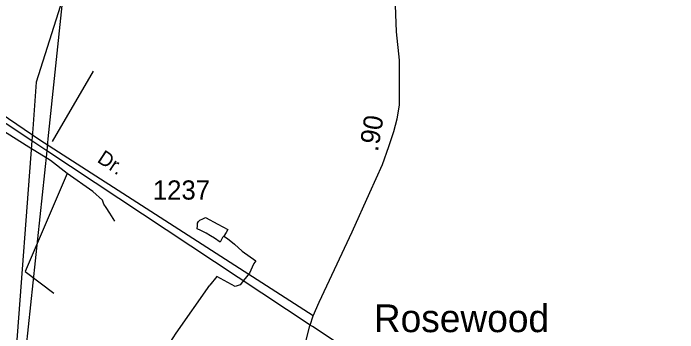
# Model space of a CAD drawing. Extents: x 2206922 to 2357709, y 510027 to 673830.
# Drawn here: x 2275145 to 2279467, y 607597 to 609677 of the extents above; entities that cross this region are included whole.
import ezdxf

# ---------------------------------------------------------------- set-up
doc = ezdxf.new("R2010")
doc.units = 0
for name, color, linetype in [('Exist Boundary Political Urban Extension UEB', 7, 'Continuous'), ('Exist Civil Demographics City Label', 7, 'Continuous'), ('Exist Hydrographic Creek Single Shore', 7, 'Continuous'), ('Exist Hydrographic Misc Water Feature', 7, 'Continuous'), ('Exist Railroad Mainline', 7, 'Continuous'), ('Exist Road Non-System Type 51', 7, 'Continuous'), ('Exist Road Primary NC Attributed', 7, 'Continuous'), ('Exist Road Primary NC Mileage Hundredths English Label', 7, 'Continuous'), ('Exist Road Secondary Type 51 Attributed', 7, 'Continuous'), ('Exist Road Secondary Type 51 Label', 7, 'Continuous'), ('Exist Road Secondary Type 51 Number Label', 7, 'Continuous'), ('Exist Utilities Electrical Transmission Line', 7, 'Continuous')]:
    doc.layers.add(name, color=color, linetype=linetype)

msp = doc.modelspace()

# ---------------------------------------------------------------- linework, layer by layer
at = {"layer": 'Exist Boundary Political Urban Extension UEB'}
for p, q in [((2275272.2, 608924.2), (2275266.2, 608845.4)), ((2275266.2, 608845.4), (2275143.8, 607237.3))]:
    msp.add_line(p, q, dxfattribs=at)
msp.add_lwpolyline([(2275466.5, 609770.2), (2275295.2, 609227.4), (2275272.2, 608924.2)], dxfattribs=at)
at = {"layer": 'Exist Hydrographic Creek Single Shore'}
msp.add_lwpolyline([(2275482.5, 602914), (2275367.6, 603398.5), (2275023.5, 604563.1), (2274947.7, 604653.2), (2274904.6, 604854.2), (2274802.5, 605059.5), (2274800.7, 605269.5), (2274932.5, 605453.7), (2275188.6, 605665), (2275493.5, 605990.1), (2275598.7, 606128.4), (2275699.6, 606261.3), (2275813.6, 606485.4), (2275951.6, 606863), (2276114.1, 607114.1), (2276154, 607168.5), (2276008.9, 607270.2), (2276088.7, 607411.7), (2276204.8, 607593.2), (2276424.7, 607906.1)], dxfattribs=at)
at = {"layer": 'Exist Hydrographic Misc Water Feature'}
for points in [[(2275804.9, 608324.2), (2275772.6, 608375.4), (2275748.6, 608413), (2275735.3, 608433.4), (2275724.7, 608460.9), (2275663.1, 608515.7), (2275496.2, 608633.4), (2275386.9, 608717.8), (2275229.8, 608816.1), (2275082.8, 608908.8), (2275017, 608952), (2274956.3, 608995.6), (2274931.3, 609008.4), (2274886.9, 608970.8), (2274787.7, 608905.8), (2274726.1, 608864.7), (2274688.5, 608847.6), (2274620.1, 608823.6), (2274585.7, 608766.1)], [(2275496.2, 608633.4), (2275222, 607995.6), (2275410.1, 607855.3)], [(2276506, 608217.6), (2276491.2, 608186.5), (2276454.2, 608213.2), (2276429, 608228), (2276400.8, 608244.3), (2276365.3, 608262.1), (2276341.5, 608274), (2276343, 608291.8), (2276343, 608311), (2276350.4, 608321.4), (2276359.3, 608328.8), (2276377.1, 608339.2), (2276394.9, 608348.1), (2276476.4, 608303.6), (2276541.6, 608268), (2276529.7, 608248.8), (2276514.9, 608225), (2276506, 608217.6)], [(2276514.9, 608225), (2276538.9, 608210.8), (2276583.6, 608173.3), (2276633.8, 608127.6), (2276723.5, 608065.1), (2276709, 608046.9), (2276698.6, 608024.5), (2276682.6, 607984.4), (2276643, 607936), (2276621.3, 607907.7), (2276589.3, 607898.1), (2276469.6, 607963.5), (2276424.7, 607906.1)]]:
    msp.add_lwpolyline(points, dxfattribs=at)
at = {"layer": 'Exist Railroad Mainline'}
for points in [[(2277075.8, 607647), (2275362.6, 608781.5), (2275266.2, 608845.4), (2273928.2, 609731.4), (2272391.5, 610753.3), (2270229, 612191.5), (2265356.3, 615416.5), (2265047.6, 615620.9), (2265047, 615621.2)], [(2279466.6, 606053.8), (2278731.4, 606546.2), (2277092, 607636.3), (2277075.8, 607647)]]:
    msp.add_lwpolyline(points, dxfattribs=at)
at = {"layer": 'Exist Road Non-System Type 51'}
msp.add_line((2275665.1, 609300.1), (2275397.7, 608841.7), dxfattribs=at)
at = {"layer": 'Exist Road Primary NC Attributed'}
msp.add_line((2277075.8, 607647), (2277096.7, 607707.3), dxfattribs=at)
for points in [[(2277096.7, 607707.3), (2277134.6, 607796.6), (2277234.5, 608009.4), (2277350.1, 608254.4), (2277463.6, 608509.2), (2277545.9, 608691.9), (2277588.8, 608808.4), (2277619.8, 608906.5), (2277641.1, 608990.6), (2277658.3, 609078.9), (2277657.3, 609180.8), (2277658.1, 609372.5), (2277637.8, 609556.3), (2277628.4, 609787.8)], [(2276853.2, 606686.5), (2276918.2, 606993), (2276968.2, 607201.3), (2277014.1, 607415.5), (2277047, 607537.8), (2277072, 607636.1), (2277075.8, 607647)]]:
    msp.add_lwpolyline(points, dxfattribs=at)
at = {"layer": 'Exist Road Secondary Type 51 Attributed'}
msp.add_lwpolyline([(2277096.7, 607707.3), (2275318.8, 608849.9), (2273590.4, 610029), (2272510.7, 610753.3), (2271787.3, 611238.6), (2271619.8, 611340.2), (2271528.9, 611405.5)], dxfattribs=at)
at = {"layer": 'Exist Utilities Electrical Transmission Line'}
for p, q in [((2275466.5, 609770.2), (2275370.8, 608859.4)), ((2275370.8, 608859.4), (2275362.6, 608781.5)), ((2275362.6, 608781.5), (2275198.4, 607219.1))]:
    msp.add_line(p, q, dxfattribs=at)

# ---------------------------------------------------------------- texts
at = {"layer": 'Exist Civil Demographics City Label'}
msp.add_text('Rosewood', height=180.45, dxfattribs=at).set_placement((2277490.2, 607600.5))
at = {"layer": 'Exist Road Primary NC Mileage Hundredths English Label'}
msp.add_text('.90', height=125, rotation=80.6002, dxfattribs=at).set_placement((2277516.5, 608771.7))
at = {"layer": 'Exist Road Secondary Type 51 Label'}
msp.add_text('Dr.', height=95, rotation=326.7374, dxfattribs=at).set_placement((2275685, 608712.1))
at = {"layer": 'Exist Road Secondary Type 51 Number Label'}
msp.add_text('1237', height=125, dxfattribs=at).set_placement((2276053.1, 608463.6))

doc.saveas('drawing.dxf')
